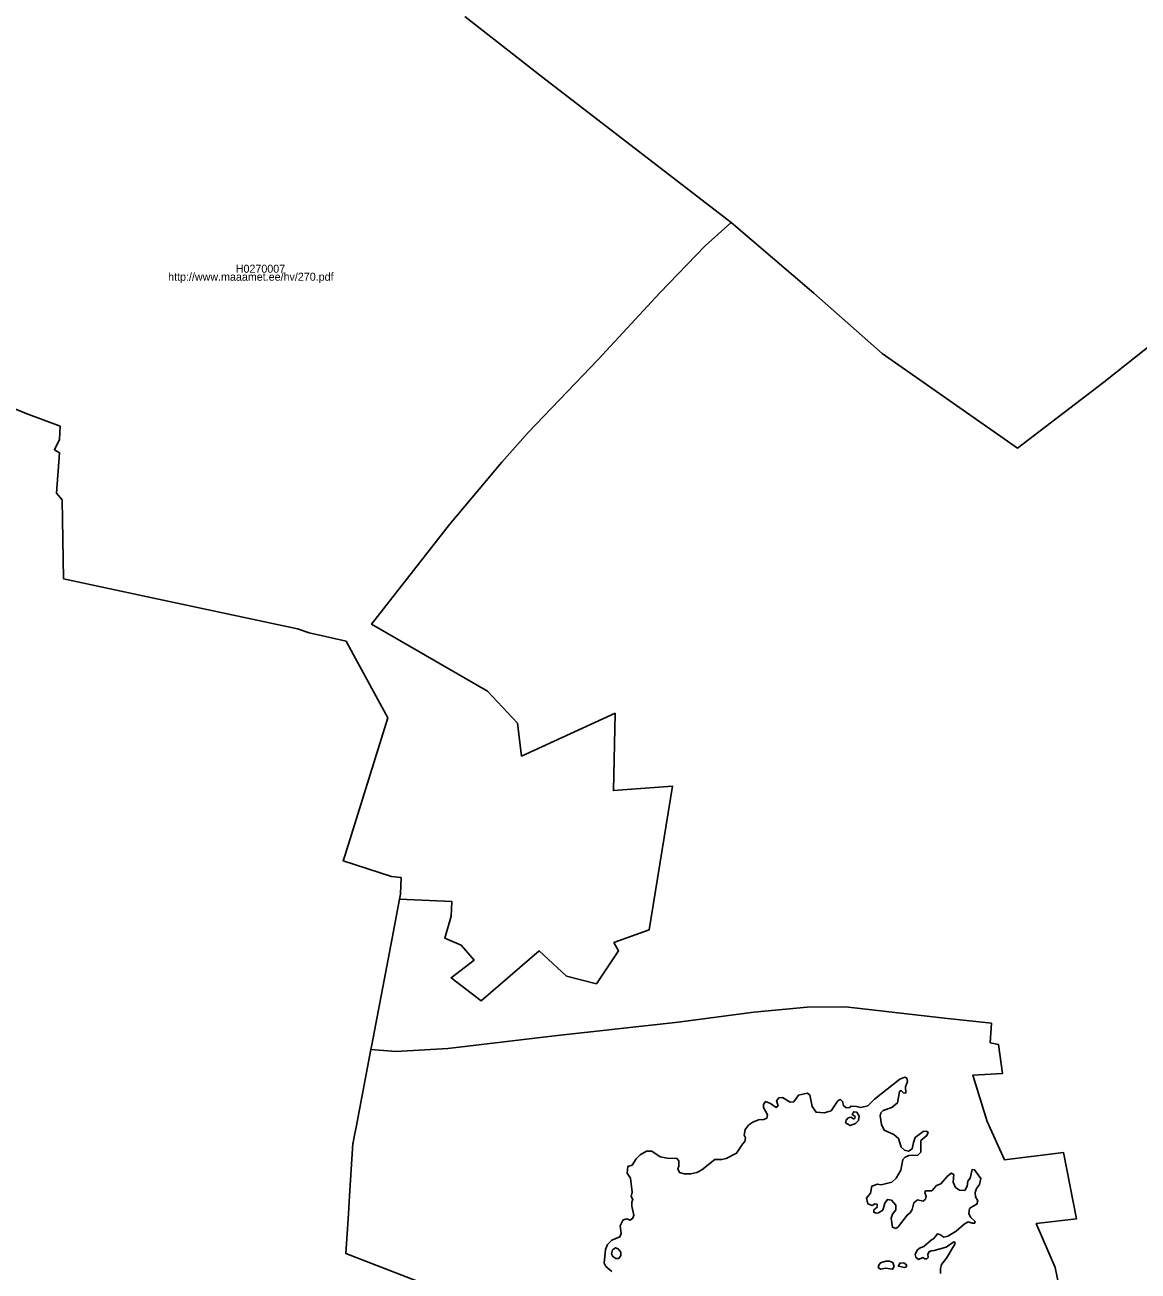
# Model space of a CAD drawing. Extents: x 369010 to 739155, y 6377141 to 6634081.
# Drawn here: x 411752 to 415228, y 6457361 to 6461254 of the extents above; entities that cross this region are included whole.
import ezdxf

# ---------------------------------------------------------------- set-up
doc = ezdxf.new("R2010")
doc.units = 0
for name, color, linetype in [('H_LINK', 7, 'Continuous'), ('H_PIIR', 7, 'Continuous'), ('H_TUNNUS', 7, 'Continuous')]:
    doc.layers.add(name, color=color, linetype=linetype)

msp = doc.modelspace()

# ---------------------------------------------------------------- linework, layer by layer
at = {"layer": 'H_PIIR'}
for points in [[(413125.2201, 6461280.37), (413369.67, 6461089.44), (413957.1599, 6460637.2499), (413876.5501, 6460564.3), (413735.1101, 6460417.0801), (413541.63, 6460208.84), (413323.83, 6459980.7099), (413241.7901, 6459887.8699), (413077.73, 6459692.9001), (412834.28, 6459382.2), (413196.1399, 6459172.4701), (413289.96, 6459072.4899), (413302.76, 6458969.58), (413595.23, 6459103.7299), (413589.7501, 6458861.8799), (413774.49, 6458875.6), (413701.27, 6458426.67), (413591.5301, 6458387.2201), (413606.16, 6458361.49), (413536.6601, 6458258.5801), (413443.37, 6458282.5899), (413357.4, 6458361.49), (413176.32, 6458205.4001), (413083.0399, 6458277.4399), (413154.37, 6458332.3299), (413114.1299, 6458378.64), (413062.9201, 6458400.9399), (413083.0399, 6458469.5499), (413084.8701, 6458515.8701), (412922.1299, 6458522.4524), (412925.15, 6458538.1946), (412926.86, 6458589.9647), (412896.97, 6458593.9447), (412745.5701, 6458642.6146), (412752.22, 6458660.9646), (412885.04, 6459089.6347), (412778.13, 6459285.7747), (412755.08, 6459328.7846), (412639.9801, 6459354.4447), (412603.5099, 6459367.1047), (412120.53, 6459470.4047), (411872.6201, 6459523.5346), (411868.42, 6459770.7846), (411850.95, 6459791.0647), (411860.05, 6459917.1546), (411843.94, 6459926.7347), (411860.05, 6459958.5147), (411861.89, 6460000.1546), (411755.3599, 6460040.0546), (411697.62, 6460063.5447)], [(415595.2299, 6460514.05), (415121.82, 6460137.47), (414851.68, 6459931.89), (414429.0999, 6460227.2401), (414215.99, 6460415.7599), (413957.1599, 6460637.2499), (413369.67, 6461089.44), (413125.2201, 6461280.37)], [(415030.3799, 6457074.34), (414969.58, 6457372.02), (414910.25, 6457509.18), (415035.74, 6457523.8899), (414995.1399, 6457731.57), (414811.1099, 6457708.46), (414757.3999, 6457828.36), (414712.76, 6457973.14), (414804.8201, 6457977.94), (414792.0299, 6458069.06), (414766.46, 6458073.8601), (414770.2901, 6458135.0101), (414623.7001, 6458150.6101), (414314.2799, 6458186.58), (414195.37, 6458185.38), (414028.33, 6458169.83), (413791.79, 6458138.65), (413406.1399, 6458095.63), (413072.43, 6458056.66), (412911.33, 6458046.47), (412832.1744, 6458053.1006), (412835.0001, 6458067.9446), (412898.79, 6458400.7946), (412922.1299, 6458522.4524), (413084.8701, 6458515.8701), (413083.0399, 6458469.5499), (413062.9201, 6458400.9399), (413114.1299, 6458378.64), (413154.37, 6458332.3299), (413083.0399, 6458277.4399), (413176.32, 6458205.4001), (413357.4, 6458361.49), (413443.37, 6458282.5899), (413536.6601, 6458258.5801), (413606.16, 6458361.49), (413591.5301, 6458387.2201), (413701.27, 6458426.67), (413774.49, 6458875.6), (413589.7501, 6458861.8799), (413595.23, 6459103.7299), (413302.76, 6458969.58), (413289.96, 6459072.4899), (413196.1399, 6459172.4701), (412834.28, 6459382.2), (413077.73, 6459692.9001), (413241.7901, 6459887.8699), (413323.83, 6459980.7099), (413541.63, 6460208.84), (413735.1101, 6460417.0801), (413876.5501, 6460564.3), (413957.1599, 6460637.2499), (414215.99, 6460415.7599), (414429.0999, 6460227.2401), (414851.68, 6459931.89), (415121.82, 6460137.47), (415595.2299, 6460514.05)], [(411697.62, 6460063.5447), (411755.3599, 6460040.0546), (411861.89, 6460000.1546), (411860.05, 6459958.5147), (411843.94, 6459926.7347), (411860.05, 6459917.1546), (411850.95, 6459791.0647), (411868.42, 6459770.7846), (411872.6201, 6459523.5346), (412120.53, 6459470.4047), (412603.5099, 6459367.1047), (412639.9801, 6459354.4447), (412755.08, 6459328.7846), (412778.13, 6459285.7747), (412885.04, 6459089.6347), (412752.22, 6458660.9646), (412745.5701, 6458642.6146), (412896.97, 6458593.9447), (412926.86, 6458589.9647), (412925.15, 6458538.1946), (412922.1299, 6458522.4524), (412898.79, 6458400.7946), (412835.0001, 6458067.9446), (412832.1744, 6458053.1006), (412786.0501, 6457810.7947), (412781.06, 6457785.7046), (412776.48, 6457762.3947), (412775.85, 6457759.3246), (412765.54, 6457595.5046), (412762.04, 6457539.7247), (412753.94, 6457416.1046), (413084.98, 6457287.5547)], [(413084.98, 6457287.5547), (412753.94, 6457416.1046), (412762.04, 6457539.7247), (412765.54, 6457595.5046), (412775.85, 6457759.3246), (412776.48, 6457762.3947), (412781.06, 6457785.7046), (412786.0501, 6457810.7947), (412832.1744, 6458053.1006), (412911.33, 6458046.47), (413072.43, 6458056.66), (413406.1399, 6458095.63), (413791.79, 6458138.65), (414028.33, 6458169.83), (414195.37, 6458185.38), (414314.2799, 6458186.58), (414623.7001, 6458150.6101), (414770.2901, 6458135.0101), (414766.46, 6458073.8601), (414792.0299, 6458069.06), (414804.8201, 6457977.94), (414712.76, 6457973.14), (414757.3999, 6457828.36), (414811.1099, 6457708.46), (414995.1399, 6457731.57), (415035.74, 6457523.8899), (414910.25, 6457509.18), (414969.58, 6457372.02), (415030.3799, 6457074.34)], [(414611.5099, 6457353.7146), (414610.9199, 6457369.3046), (414614.74, 6457381.6647), (414629.8899, 6457401.3847), (414656.37, 6457444.3446), (414657.25, 6457449.6447), (414652.84, 6457451.9947), (414628.7099, 6457435.5146), (414591.3501, 6457424.6346), (414582.23, 6457423.7447), (414575.47, 6457420.5146), (414571.94, 6457413.1546), (414572.8199, 6457403.4447), (414568.11, 6457399.0347), (414561.9301, 6457399.3246), (414556.0499, 6457402.8546), (414542.52, 6457397.2647), (414534.58, 6457404.0347), (414532.5201, 6457412.5646), (414538.4, 6457426.1047), (414546.05, 6457432.8646), (414559.29, 6457437.8746), (414583.41, 6457458.1746), (414589.29, 6457461.7046), (414601.94, 6457477.2947), (414609.45, 6457475.2347), (414621.51, 6457466.6946), (414634.16, 6457470.2346), (414660.5801, 6457485.4547), (414684.93, 6457507.1046), (414697.5601, 6457514.3247), (414710.1801, 6457510.7146), (414717.85, 6457510.2647), (414719.2, 6457515.2246), (414706.1199, 6457527.8446), (414700.2599, 6457539.1247), (414702.0699, 6457556.2646), (414711.54, 6457563.0246), (414724.6101, 6457569.3446), (414728.22, 6457580.6147), (414720.1001, 6457593.2446), (414719.2, 6457606.3246), (414723.71, 6457618.9546), (414732.7301, 6457631.5847), (414736.7901, 6457649.6246), (414717.4, 6457677.5847), (414709.73, 6457678.0346), (414703.8701, 6457650.9747), (414696.65, 6457641.5046), (414694.85, 6457625.7147), (414687.1901, 6457612.1846), (414670.2799, 6457613.5347), (414658.55, 6457622.1046), (414651.3401, 6457638.3447), (414653.1401, 6457662.2446), (414645.0301, 6457666.7547), (414631.95, 6457655.9246), (414612.1101, 6457633.8247), (414599.03, 6457627.9647), (414584.15, 6457611.7347), (414564.7599, 6457611.2847), (414562.06, 6457605.8646), (414566.5601, 6457593.6946), (414564.3101, 6457585.5746), (414556.6399, 6457579.2546), (414539.06, 6457583.3146), (414528.4601, 6457574.2947), (414522.5999, 6457553.5547), (414516.2899, 6457542.7247), (414506.82, 6457535.9646), (414479.3099, 6457498.9846), (414472.1, 6457493.5647), (414461.27, 6457497.6247), (414456.76, 6457525.5846), (414461.27, 6457538.2146), (414471.65, 6457552.1946), (414471.65, 6457566.6246), (414458.5699, 6457581.9647), (414445.49, 6457584.6647), (414436.92, 6457572.4947), (414431.5101, 6457551.2947), (414417.5299, 6457542.2746), (414409.87, 6457541.3747), (414402.6501, 6457544.5346), (414403.1, 6457551.7447), (414413.0199, 6457560.3146), (414413.48, 6457569.3346), (414406.7101, 6457570.6846), (414398.1401, 6457565.2746), (414384.62, 6457570.6846), (414379.6601, 6457588.7247), (414393.18, 6457604.0646), (414397.24, 6457626.1647), (414414.8301, 6457632.0247), (414425.6499, 6457630.2247), (414458.8, 6457638.3447), (414472.78, 6457650.9647), (414487.21, 6457675.7747), (414493.97, 6457709.1446), (414501.18, 6457716.3647), (414512.01, 6457721.7746), (414540.42, 6457723.1247), (414549.8801, 6457732.6046), (414550.3399, 6457768.6847), (414568.8201, 6457784.0146), (414572.43, 6457794.3846), (414566.5701, 6457797.9946), (414557.1, 6457797.0947), (414532.3, 6457778.6047), (414526.44, 6457762.3647), (414522.83, 6457742.9746), (414511.0999, 6457735.3047), (414498.9299, 6457738.4646), (414488.1101, 6457747.4847), (414480.4399, 6457774.5447), (414466.0099, 6457787.6246), (414435.8, 6457801.1547), (414427.23, 6457819.1946), (414423.17, 6457846.2546), (414424.97, 6457855.2747), (414432.6399, 6457862.9447), (414459.6899, 6457871.5147), (414476.83, 6457885.9447), (414483.14, 6457921.5747), (414488.5499, 6457924.7246), (414496.2201, 6457917.5146), (414502.5301, 6457917.0647), (414501.63, 6457936.4546), (414507.94, 6457953.1346), (414506.14, 6457963.0646), (414499.82, 6457966.2147), (414484.0401, 6457960.3547), (414405.33, 6457897.4847), (414383.98, 6457876.6547), (414362.12, 6457871.4547), (414349.11, 6457874.5746), (414331.93, 6457875.6147), (414326.73, 6457871.4547), (414316.32, 6457870.4147), (414307.9899, 6457877.6946), (414305.39, 6457890.7146), (414298.62, 6457896.4347), (414290.8101, 6457892.7947), (414269.4701, 6457861.5647), (414247.61, 6457854.7947), (414222.6301, 6457856.8746), (414210.66, 6457875.1046), (414203.37, 6457911.0246), (414195.0401, 6457916.2246), (414167.45, 6457910.4946), (414152.8801, 6457889.1546), (414141.9501, 6457888.1147), (414118.01, 6457902.6947), (414106.0299, 6457901.6446), (414099.2701, 6457892.2747), (414103.95, 6457877.1847), (414098.23, 6457871.4547), (414080.53, 6457883.9546), (414064.91, 6457890.1946), (414058.1499, 6457881.3447), (414058.1499, 6457871.9747), (414070.64, 6457848.5546), (414068.5599, 6457838.1347), (414059.19, 6457834.4947), (414042.5299, 6457833.4547), (414024.8401, 6457825.6446), (414012.86, 6457817.8347), (414000.89, 6457803.2646), (413998.2901, 6457785.5647), (414002.45, 6457777.2346), (414000.37, 6457765.7746), (413993.0801, 6457757.4546), (413974.35, 6457728.8146), (413942.07, 6457712.6846), (413927.49, 6457709.0446), (413906.67, 6457709.5646), (413865.5501, 6457677.2846), (413850.4599, 6457668.4347), (413831.2, 6457664.2747), (413810.38, 6457664.2747), (413795.81, 6457668.4347), (413791.1201, 6457679.8947), (413794.24, 6457688.7446), (413794.24, 6457704.8747), (413788, 6457712.6846), (413757.81, 6457713.2046), (413735.43, 6457717.8947), (413709.92, 6457735.0746), (413693.0001, 6457735.5846), (413673.74, 6457724.1346), (413660.7301, 6457711.6447), (413648.76, 6457691.8646), (413635.2299, 6457687.6946), (413632.62, 6457666.3546), (413642.7701, 6457651.2546), (413648.4899, 6457607.0046), (413644.85, 6457593.4647), (413650.58, 6457584.6147), (413646.93, 6457575.7646), (413647.4501, 6457563.2747), (413653.6999, 6457535.6847), (413650.58, 6457525.7947), (413641.7301, 6457520.0647), (413631.5, 6457524.3346), (413620.2199, 6457521.2047), (413610.7, 6457501.7047), (413613.65, 6457477.8747), (413609.8199, 6457468.1647), (413584.9599, 6457457.5646), (413571.43, 6457443.4447), (413565.5401, 6457428.1446), (413560.8401, 6457385.4846), (413566.43, 6457375.1847), (413584.3699, 6457359.5947)]]:
    msp.add_lwpolyline(points, dxfattribs=at)
for points in [[(414357.1433, 6457844.8745), (414354.8263, 6457830.9721), (414345.8891, 6457821.3729), (414328.6767, 6457815.5804), (414315.1054, 6457824.1866), (414316.9259, 6457832.2962), (414323.215, 6457839.9095), (414330.9937, 6457841.2334), (414339.6, 6457836.2683), (414343.572, 6457837.7579), (414344.3996, 6457843.5505), (414335.4622, 6457850.3362), (414340.4275, 6457858.4458), (414349.8612, 6457857.4529)], [(413606.9137, 6457400.1652), (413596.818, 6457400.1652), (413588.3772, 6457406.1234), (413584.2396, 6457414.8951), (413587.2188, 6457426.977), (413596.3214, 6457433.7626), (413604.5967, 6457429.9559), (413612.7063, 6457419.8602), (413612.7063, 6457409.1025)], [(414466.8724, 6457374.8431), (414461.4108, 6457366.7335), (414440.2263, 6457369.5471), (414424.3379, 6457366.8989), (414416.8903, 6457372.0296), (414418.3799, 6457379.3118), (414424.3379, 6457386.4284), (414440.7228, 6457392.221), (414452.4736, 6457391.7246), (414462.7349, 6457387.2559)], [(414505.104, 6457374.3467), (414498.3182, 6457372.0296), (414479.7819, 6457376.0017), (414483.9194, 6457385.4355), (414496.9941, 6457386.4284), (414505.104, 6457380.4704)]]:
    msp.add_lwpolyline(points, close=True, dxfattribs=at)

# ---------------------------------------------------------------- texts
at = {"layer": 'H_LINK'}
msp.add_text('http://www.maaamet.ee/hv/270.pdf', height=25, rotation=360, dxfattribs=at).set_placement((412199.1563, 6460454.8479))
at = {"layer": 'H_TUNNUS'}
msp.add_text('H0270007', height=25, rotation=360, dxfattribs=at).set_placement((412410.3852, 6460479.8479))

doc.saveas('drawing.dxf')
